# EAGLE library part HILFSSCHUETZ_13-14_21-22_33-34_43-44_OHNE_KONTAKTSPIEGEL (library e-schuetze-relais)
Hilfsschütz mit 3 Schließern, 1 Öffner ohne Kontaktspiegel
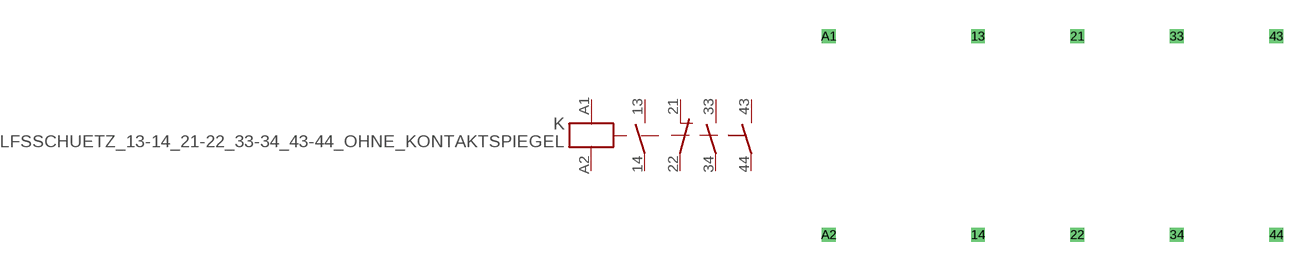
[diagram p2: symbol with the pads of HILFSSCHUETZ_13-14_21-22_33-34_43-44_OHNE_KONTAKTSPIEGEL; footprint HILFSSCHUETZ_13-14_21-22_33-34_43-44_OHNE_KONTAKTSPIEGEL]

Designator prefix K

## HILFSSCHUETZ_13-14_21-22_33-34_43-44_OHNE_KONTAKTSPIEGEL  [HILFSSCHUETZ_13-14_21-22_33-34_43-44_OHNE_KONTAKTSPIEGEL]
13  13  pas
14  14  pas
21  21  pas
22  22  pas
33  33  pas
34  34  pas
43  43  pas
44  44  pas
A1  A1  in
A2  A2  in

## Footprint HILFSSCHUETZ_13-14_21-22_33-34_43-44_OHNE_KONTAKTSPIEGEL (pad centres in mm)
Dummy
drill 0.2 pad 0.6 square: 13 7.62,5.08; 14 7.62,-5.08; 21 12.7,5.08; 22 12.7,-5.08; 33 17.78,5.08; 34 17.78,-5.08; 43 22.86,5.08; 44 22.86,-5.08; A1 0,5.08; A2 0,-5.08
